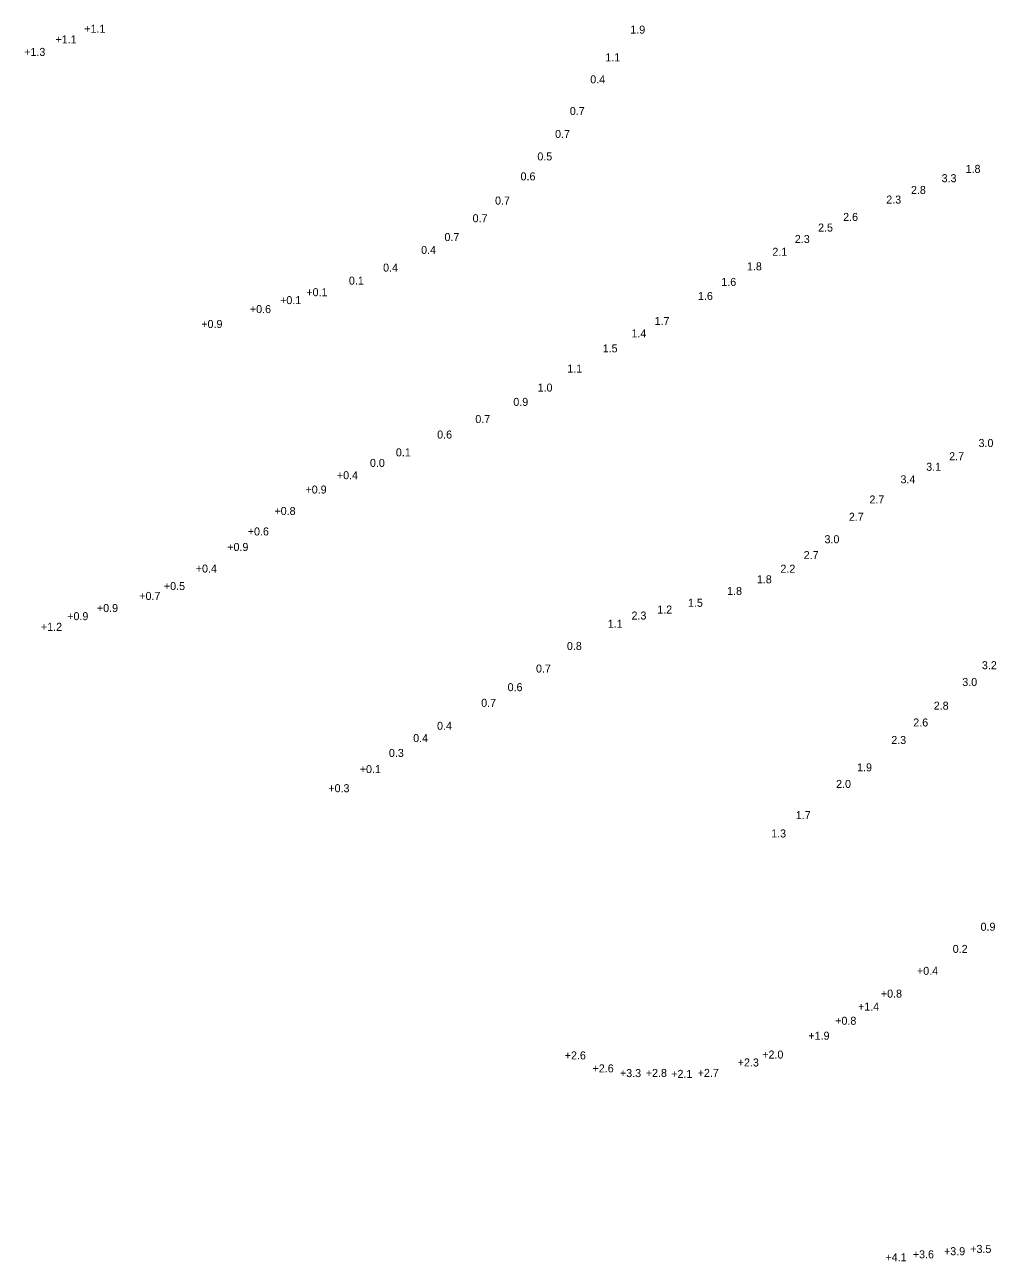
# Model space of a CAD drawing. Extents: x 837127 to 848654, y 3074248 to 3079868.
# Drawn here: x 845294.6 to 845673.9, y 3078149.9 to 3078632.6 of the extents above; entities that cross this region are included whole.
import ezdxf

# ---------------------------------------------------------------- set-up
doc = ezdxf.new("R2010")
doc.units = 0
doc.layers.add('V-HYDS-SOUN', color=7, linetype='Continuous')

msp = doc.modelspace()

# ---------------------------------------------------------------- texts
at = {"layer": 'V-HYDS-SOUN'}
for s, p in [('+1.1 ', (845317.84, 3078629.47)), ('1.9', (845531.01, 3078629.13)), ('+1.1 ', (845306.59, 3078625.31)), ('+1.3 ', (845294.39, 3078620.42)), ('1.1', (845521.24, 3078618.29)), ('0.4', (845515.38, 3078609.72)), ('0.7', (845507.4, 3078597.36)), ('0.7', (845501.64, 3078588.39)), ('0.5', (845494.73, 3078579.63)), ('1.8', (845661.91, 3078574.77)), ('0.6', (845488.17, 3078571.84)), ('3.3', (845652.54, 3078571.13)), ('2.8', (845640.58, 3078566.54)), ('0.7', (845478.21, 3078562.39)), ('2.3', (845630.94, 3078562.78)), ('0.7', (845469.45, 3078555.49)), ('2.6', (845614.11, 3078556.01)), ('2.5', (845604.32, 3078551.86)), ('0.7', (845458.46, 3078548.16)), ('2.3', (845595.25, 3078547.39)), ('0.4', (845449.34, 3078543.12)), ('2.1', (845586.47, 3078542.4)), ('0.4', (845434.5, 3078536.23)), ('1.8', (845576.55, 3078536.71)), ('0.1', (845421.16, 3078531.14)), ('+0.1 ', (845404.54, 3078526.63)), ('1.6', (845566.54, 3078530.64)), ('+0.1 ', (845394.3, 3078523.54)), ('1.6', (845557.43, 3078525.15)), ('+0.6 ', (845382.5, 3078520.03)), ('+0.9 ', (845363.54, 3078514.23)), ('1.7', (845540.49, 3078515.38)), ('1.4', (845531.47, 3078510.56)), ('1.5', (845520.24, 3078504.71)), ('1.1', (845506.39, 3078496.82)), ('1.0', (845494.82, 3078489.4)), ('0.9', (845485.34, 3078483.82)), ('0.7', (845470.51, 3078477.12)), ('0.6', (845455.61, 3078471.07)), ('0.1', (845439.5, 3078464.11)), ('3.0', (845666.96, 3078467.76)), (' 0.0', (845428.2, 3078460)), ('3.1', (845646.53, 3078458.48)), ('2.7', (845655.5, 3078462.6)), ('+0.4 ', (845416.48, 3078455.2)), ('3.4', (845636.5, 3078453.6)), ('+0.9 ', (845404.2, 3078449.6)), ('2.7', (845624.37, 3078445.72)), ('+0.8 ', (845392.09, 3078441.23)), ('2.7', (845616.33, 3078438.96)), ('+0.6 ', (845381.67, 3078433.25)), ('3.0', (845606.83, 3078430.2)), ('+0.9 ', (845373.66, 3078427.19)), ('2.7', (845598.7, 3078424.02)), ('+0.4 ', (845361.37, 3078418.77)), ('2.2', (845589.61, 3078418.69)), ('+0.5 ', (845348.93, 3078411.92)), ('1.8', (845580.42, 3078414.55)), ('+0.7 ', (845339.32, 3078408.09)), ('1.5', (845553.51, 3078405.39)), ('1.8', (845568.81, 3078410.02)), ('+0.9 ', (845322.78, 3078403.35)), ('2.3', (845531.49, 3078400.42)), ('1.2', (845541.54, 3078402.76)), ('+1.2 ', (845300.92, 3078396.01)), ('+0.9 ', (845311.19, 3078400.18)), ('1.1', (845522.2, 3078397.22)), ('0.8', (845506.27, 3078388.55)), ('0.7', (845494.19, 3078379.74)), ('3.2', (845668.28, 3078381.03)), ('0.6', (845483.12, 3078372.46)), ('3.0', (845660.61, 3078374.5)), ('0.7', (845472.8, 3078366.34)), ('2.8', (845649.47, 3078365.24)), ('0.4', (845455.57, 3078357.37)), ('2.6', (845641.48, 3078358.68)), ('0.4', (845446.25, 3078352.58)), ('2.3', (845632.89, 3078351.84)), ('0.3', (845436.78, 3078346.79)), ('+0.1 ', (845425.4, 3078340.49)), ('1.9', (845619.55, 3078341.16)), ('+0.3 ', (845413.13, 3078333.02)), ('2.0', (845611.35, 3078334.69)), ('1.7', (845595.62, 3078322.52)), ('1.3', (845586.01, 3078315.36)), ('0.9', (845667.75, 3078278.95)), ('0.2', (845656.88, 3078270.29)), ('+0.4 ', (845642.93, 3078261.74)), ('+0.8 ', (845628.83, 3078252.84)), ('+1.4 ', (845619.9, 3078247.77)), ('+0.8 ', (845611, 3078242.25)), ('+1.9 ', (845600.54, 3078236.41)), ('+2.6 ', (845505.41, 3078228.73)), ('+2.0 ', (845582.52, 3078229.05)), ('+2.6 ', (845516.27, 3078223.66)), ('+3.3 ', (845526.98, 3078221.82)), ('+2.8 ', (845537.06, 3078221.88)), ('+2.7 ', (845557.31, 3078221.89)), ('+2.3 ', (845572.95, 3078225.96)), ('+2.1 ', (845546.99, 3078221.51)), ('+4.1 ', (845630.63, 3078149.93)), ('+3.6 ', (845641.31, 3078151.08)), ('+3.9 ', (845653.48, 3078152.3)), ('+3.5 ', (845663.72, 3078153.18))]:
    msp.add_text(s, height=3.125, dxfattribs=at).set_placement(p)

doc.saveas('drawing.dxf')
